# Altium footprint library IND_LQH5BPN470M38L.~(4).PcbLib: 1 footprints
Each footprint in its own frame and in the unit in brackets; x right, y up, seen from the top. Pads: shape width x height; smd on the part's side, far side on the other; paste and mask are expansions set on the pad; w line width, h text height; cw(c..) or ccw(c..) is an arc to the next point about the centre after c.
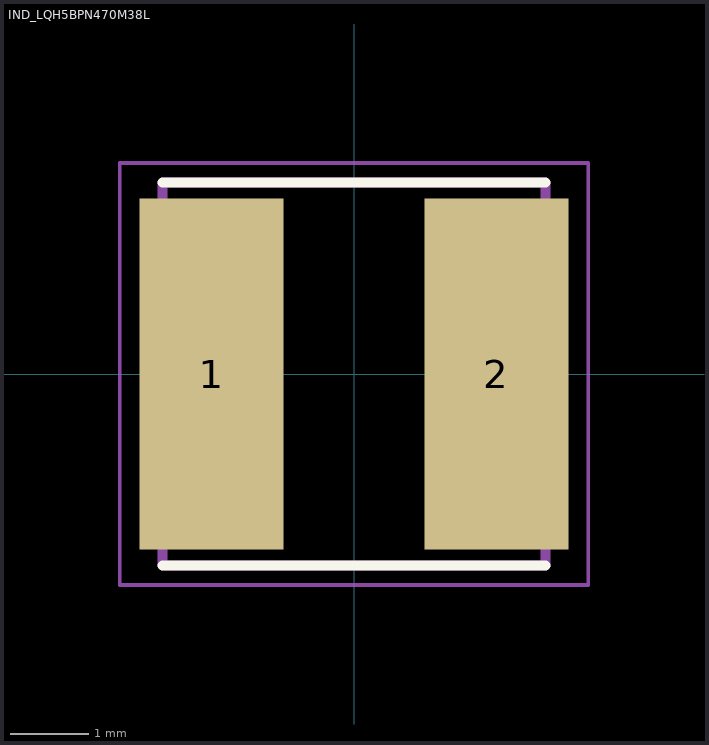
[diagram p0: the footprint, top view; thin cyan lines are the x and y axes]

## IND_LQH5BPN470M38L [mm]
pads (2):
  rect 1.85x4.5 smd: 1(-1.825,0) 2(1.825,0)
Top Overlay:
  lines w0.127: -2.45,-2.45 2.45,-2.45 ; -2.45,2.45 2.45,2.45
Mechanical 13:
  lines w0.127: -2.45,-2.45 -2.45,2.45 2.45,2.45 2.45,-2.45 -2.45,-2.45
Mechanical 15:
  lines w0.05: -3,-2.7 -3,2.7 3,2.7 3,-2.7 -3,-2.7
3D body "LQH5BPN100M38L.STEP": height 2.45, standoff -2.45, extent -2.45,-2.032 2.45,1.968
